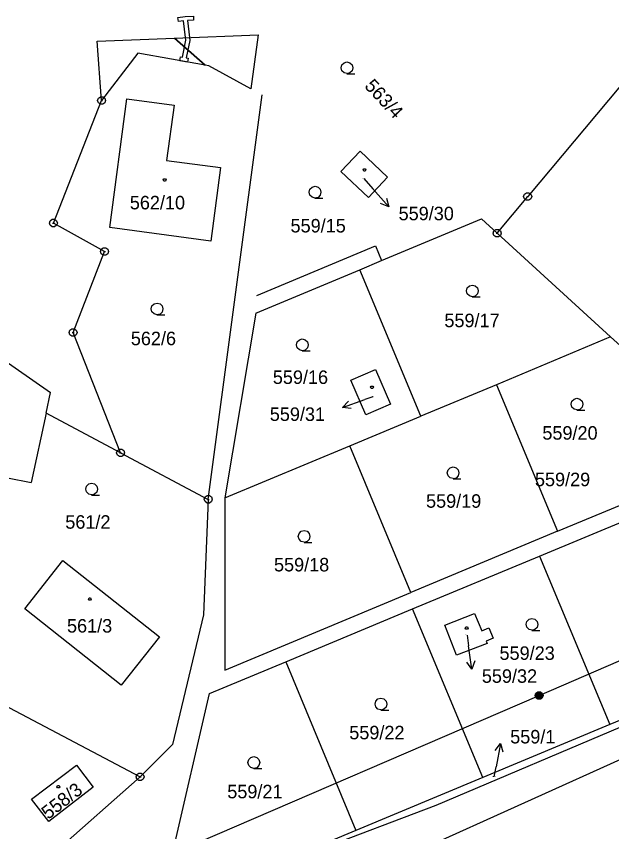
# Model space of a CAD drawing. Extents: x -759699 to -757730, y -1172308 to -1170857.
# Drawn here: x -759171.2 to -759096.2, y -1171620.5 to -1171517.8 of the extents above; entities that cross this region are included whole.
import ezdxf

# ---------------------------------------------------------------- set-up
doc = ezdxf.new("R2010")
doc.units = 0
for name, color, linetype in [('Vrstva 1', 7, 'Continuous'), ('Vrstva 12', 7, 'Continuous'), ('Vrstva 13', 7, 'Continuous'), ('Vrstva 2', 7, 'Continuous'), ('Vrstva 3', 7, 'Continuous'), ('Vrstva 4', 7, 'Continuous'), ('Vrstva 5', 7, 'Continuous'), ('Vrstva 6', 7, 'Continuous'), ('Vrstva 7', 7, 'Continuous'), ('Vrstva 8', 7, 'Continuous')]:
    doc.layers.add(name, color=color, linetype=linetype)

msp = doc.modelspace()

# ---------------------------------------------------------------- linework, layer by layer
at = {"layer": 'Vrstva 1'}
for p, q in [((-759093.5, -1171524.55), (-759106.82, -1171540.51)), ((-759159.44, -1171544.39), (-759157.28, -1171528.2)), ((-759157.28, -1171528.2), (-759151.34, -1171528.99)), ((-759147.03, -1171578.64), (-759140.26, -1171527.68)), ((-759140.26, -1171527.68), (-759140.26, -1171527.68)), ((-759140.26, -1171527.68), (-759140.26, -1171527.68)), ((-759166.53, -1171543.84), (-759160.46, -1171528.4)), ((-759160.46, -1171528.4), (-759160.46, -1171528.4)), ((-759151.34, -1171528.99), (-759152.28, -1171535.96)), ((-759127.92, -1171534.77), (-759130.34, -1171537.33)), ((-759127.92, -1171534.77), (-759124.46, -1171538.06)), ((-759152.28, -1171535.96), (-759145.48, -1171536.83)), ((-759145.48, -1171536.83), (-759146.71, -1171546.12)), ((-759130.34, -1171537.33), (-759126.87, -1171540.61)), ((-759124.46, -1171538.06), (-759126.87, -1171540.61)), ((-759110.66, -1171545.12), (-759106.82, -1171540.51)), ((-759106.82, -1171540.51), (-759106.82, -1171540.51)), ((-759125.21, -1171548.56), (-759112.63, -1171543.32)), ((-759112.63, -1171543.32), (-759112.63, -1171543.32)), ((-759112.63, -1171543.32), (-759110.66, -1171545.12)), ((-759160.09, -1171547.43), (-759166.53, -1171543.84)), ((-759146.71, -1171546.12), (-759159.44, -1171544.39)), ((-759110.66, -1171545.12), (-759096.41, -1171558.16)), ((-759140.91, -1171552.94), (-759125.98, -1171546.71)), ((-759125.98, -1171546.71), (-759125.21, -1171548.56)), ((-759164.05, -1171557.64), (-759160.09, -1171547.43)), ((-759127.97, -1171549.71), (-759125.21, -1171548.56)), ((-759141.06, -1171555.17), (-759127.97, -1171549.71)), ((-759120.29, -1171568.18), (-759127.97, -1171549.71)), ((-759140.91, -1171552.94), (-759140.91, -1171552.94)), ((-759141.06, -1171555.17), (-759144.93, -1171578.46)), ((-759179.26, -1171556.57), (-759166.9, -1171565.2)), ((-759158.07, -1171572.78), (-759164.05, -1171557.64)), ((-759096.41, -1171558.16), (-759110.76, -1171564.21)), ((-759078.48, -1171574.58), (-759096.41, -1171558.16)), ((-759129.07, -1171563.62), (-759125.97, -1171562.29)), ((-759125.97, -1171562.29), (-759124.09, -1171566.66)), ((-759127.19, -1171568.01), (-759129.07, -1171563.62)), ((-759167.45, -1171567.78), (-759166.9, -1171565.2)), ((-759110.76, -1171564.21), (-759120.29, -1171568.18)), ((-759110.76, -1171564.21), (-759103.07, -1171582.66)), ((-759124.09, -1171566.66), (-759127.19, -1171568.01)), ((-759167.45, -1171567.78), (-759169.31, -1171576.53)), ((-759158.07, -1171572.78), (-759167.45, -1171567.78)), ((-759129.22, -1171571.91), (-759120.29, -1171568.18)), ((-759144.93, -1171578.46), (-759129.22, -1171571.91)), ((-759121.53, -1171590.36), (-759129.22, -1171571.91)), ((-759158.07, -1171572.78), (-759147.03, -1171578.64)), ((-759172.32, -1171575.91), (-759169.31, -1171576.53)), ((-759103.07, -1171582.66), (-759087.39, -1171576.13)), ((-759144.93, -1171578.46), (-759144.97, -1171600.14)), ((-759147.03, -1171578.64), (-759147.64, -1171593.18)), ((-759105.35, -1171585.79), (-759089.39, -1171579.13)), ((-759103.07, -1171582.66), (-759121.53, -1171590.36)), ((-759170.14, -1171592.43), (-759165.33, -1171586.33)), ((-759165.33, -1171586.33), (-759153.19, -1171595.95)), ((-759121.32, -1171592.45), (-759105.35, -1171585.79)), ((-759105.35, -1171585.79), (-759096.5, -1171607.02)), ((-759144.97, -1171600.14), (-759121.53, -1171590.36)), ((-759158, -1171602.06), (-759170.14, -1171592.43)), ((-759137.29, -1171599.1), (-759121.32, -1171592.45)), ((-759112.47, -1171613.68), (-759121.32, -1171592.45)), ((-759147.64, -1171593.18), (-759151.53, -1171609.52)), ((-759117.27, -1171594.48), (-759113.51, -1171593)), ((-759113.51, -1171593), (-759112.58, -1171595.21)), ((-759064.19, -1171594.2), (-759118.37, -1171617.22)), ((-759115.77, -1171598.28), (-759117.27, -1171594.48)), ((-759112.58, -1171595.21), (-759111.7, -1171594.84)), ((-759111.7, -1171594.84), (-759111.17, -1171596.13)), ((-759153.19, -1171595.95), (-759158, -1171602.06)), ((-759111.93, -1171596.78), (-759115.77, -1171598.28)), ((-759111.17, -1171596.13), (-759112.04, -1171596.5)), ((-759112.04, -1171596.5), (-759111.93, -1171596.78)), ((-759146.88, -1171603.11), (-759137.29, -1171599.1)), ((-759137.29, -1171599.1), (-759128.44, -1171620.34)), ((-759080.54, -1171600.36), (-759096.5, -1171607.02)), ((-759153.26, -1171630.69), (-759146.88, -1171603.11)), ((-759172.84, -1171604.48), (-759155.62, -1171613.61)), ((-759096.5, -1171607.02), (-759112.47, -1171613.68)), ((-759151.53, -1171609.52), (-759155.62, -1171613.61)), ((-759169.27, -1171616.41), (-759163.64, -1171612.11)), ((-759163.64, -1171612.11), (-759161.51, -1171614.89)), ((-759183.56, -1171638.31), (-759155.62, -1171613.61)), ((-759112.47, -1171613.68), (-759128.44, -1171620.34)), ((-759161.51, -1171614.89), (-759167.12, -1171619.22)), ((-759167.12, -1171619.22), (-759169.27, -1171616.41)), ((-759118.37, -1171617.22), (-759136.99, -1171624.23)), ((-759128.44, -1171620.34), (-759153.26, -1171630.69))]:
    msp.add_line(p, q, dxfattribs=at)
at = {"layer": 'Vrstva 12'}
for p, q in [((-759159.44, -1171544.39), (-759157.28, -1171528.2)), ((-759157.28, -1171528.2), (-759151.34, -1171528.99)), ((-759151.34, -1171528.99), (-759152.28, -1171535.96)), ((-759127.92, -1171534.77), (-759130.34, -1171537.33)), ((-759127.92, -1171534.77), (-759124.46, -1171538.06)), ((-759152.28, -1171535.96), (-759145.48, -1171536.83)), ((-759145.48, -1171536.83), (-759146.71, -1171546.12)), ((-759130.34, -1171537.33), (-759126.87, -1171540.61)), ((-759124.46, -1171538.06), (-759126.87, -1171540.61)), ((-759146.71, -1171546.12), (-759159.44, -1171544.39)), ((-759129.07, -1171563.62), (-759125.97, -1171562.29)), ((-759125.97, -1171562.29), (-759124.09, -1171566.66)), ((-759127.19, -1171568.01), (-759129.07, -1171563.62)), ((-759124.09, -1171566.66), (-759127.19, -1171568.01)), ((-759170.14, -1171592.43), (-759165.33, -1171586.33)), ((-759165.33, -1171586.33), (-759153.19, -1171595.95)), ((-759158, -1171602.06), (-759170.14, -1171592.43)), ((-759117.27, -1171594.48), (-759113.51, -1171593)), ((-759113.51, -1171593), (-759112.58, -1171595.21)), ((-759115.77, -1171598.28), (-759117.27, -1171594.48)), ((-759112.58, -1171595.21), (-759111.7, -1171594.84)), ((-759111.7, -1171594.84), (-759111.17, -1171596.13)), ((-759153.19, -1171595.95), (-759158, -1171602.06)), ((-759111.93, -1171596.78), (-759115.77, -1171598.28)), ((-759111.17, -1171596.13), (-759112.04, -1171596.5)), ((-759112.04, -1171596.5), (-759111.93, -1171596.78)), ((-759169.27, -1171616.41), (-759163.64, -1171612.11)), ((-759163.64, -1171612.11), (-759161.51, -1171614.89)), ((-759161.51, -1171614.89), (-759167.12, -1171619.22)), ((-759167.12, -1171619.22), (-759169.27, -1171616.41))]:
    msp.add_line(p, q, dxfattribs=at)
at = {"layer": 'Vrstva 13'}
for p, q in [((-759150.86, -1171517.94), (-759149.96, -1171517.8)), ((-759150.78, -1171518.44), (-759150.86, -1171517.94)), ((-759149.96, -1171517.8), (-759148.89, -1171517.79)), ((-759148.89, -1171517.79), (-759148.89, -1171518.29)), ((-759150.16, -1171518.34), (-759150.78, -1171518.44)), ((-759149.9, -1171520.48), (-759150.16, -1171518.34)), ((-759148.89, -1171518.29), (-759149.66, -1171518.3)), ((-759149.66, -1171518.3), (-759149.4, -1171520.47)), ((-759161.02, -1171520.93), (-759151.27, -1171520.54)), ((-759160.46, -1171528.4), (-759161.02, -1171520.93)), ((-759151.27, -1171520.54), (-759140.77, -1171520.12)), ((-759147.44, -1171523.94), (-759151.27, -1171520.54)), ((-759151.27, -1171520.54), (-759147.44, -1171523.94)), ((-759150.29, -1171522.93), (-759149.86, -1171520.8)), ((-759149.86, -1171520.8), (-759149.9, -1171520.48)), ((-759149.36, -1171520.82), (-759149.8, -1171523.02)), ((-759149.4, -1171520.47), (-759149.36, -1171520.82)), ((-759140.77, -1171520.12), (-759141.67, -1171526.91)), ((-759155.89, -1171522.45), (-759160.46, -1171528.4)), ((-759147.44, -1171523.94), (-759155.89, -1171522.45)), ((-759150.63, -1171523.38), (-759150.55, -1171522.89)), ((-759150.55, -1171522.89), (-759150.29, -1171522.93)), ((-759149.8, -1171523.02), (-759149.56, -1171523.06)), ((-759149.56, -1171523.06), (-759149.65, -1171523.55)), ((-759149.65, -1171523.55), (-759150.63, -1171523.38)), ((-759146.95, -1171524.03), (-759147.44, -1171523.94)), ((-759141.67, -1171526.91), (-759146.95, -1171524.03))]:
    msp.add_line(p, q, dxfattribs=at)
at = {"layer": 'Vrstva 3'}
for points in [[(-759129.56, -1171525.01), (-759129.94, -1171524.91), (-759130.21, -1171524.64), (-759130.31, -1171524.27), (-759130.21, -1171523.9), (-759129.94, -1171523.63), (-759129.57, -1171523.53), (-759129.2, -1171523.63), (-759128.93, -1171523.9), (-759128.83, -1171524.28), (-759128.93, -1171524.66), (-759129.2, -1171524.93), (-759129.58, -1171525.03), (-759128.58, -1171525.03)], [(-759133.58, -1171540.68), (-759133.96, -1171540.58), (-759134.23, -1171540.31), (-759134.33, -1171539.94), (-759134.23, -1171539.57), (-759133.96, -1171539.3), (-759133.59, -1171539.2), (-759133.22, -1171539.3), (-759132.95, -1171539.57), (-759132.85, -1171539.95), (-759132.95, -1171540.33), (-759133.22, -1171540.6), (-759133.6, -1171540.7), (-759132.6, -1171540.7)], [(-759113.78, -1171553.12), (-759114.16, -1171553.02), (-759114.43, -1171552.75), (-759114.53, -1171552.38), (-759114.43, -1171552.01), (-759114.16, -1171551.74), (-759113.79, -1171551.64), (-759113.42, -1171551.74), (-759113.15, -1171552.01), (-759113.05, -1171552.39), (-759113.15, -1171552.77), (-759113.42, -1171553.04), (-759113.8, -1171553.14), (-759112.8, -1171553.14)], [(-759153.47, -1171555.39), (-759153.85, -1171555.29), (-759154.12, -1171555.02), (-759154.22, -1171554.65), (-759154.12, -1171554.28), (-759153.85, -1171554.01), (-759153.48, -1171553.91), (-759153.11, -1171554.01), (-759152.84, -1171554.28), (-759152.74, -1171554.66), (-759152.84, -1171555.04), (-759153.11, -1171555.31), (-759153.49, -1171555.41), (-759152.49, -1171555.41)], [(-759135.19, -1171559.91), (-759135.57, -1171559.81), (-759135.84, -1171559.54), (-759135.94, -1171559.17), (-759135.84, -1171558.8), (-759135.57, -1171558.53), (-759135.2, -1171558.43), (-759134.83, -1171558.53), (-759134.56, -1171558.8), (-759134.46, -1171559.18), (-759134.56, -1171559.56), (-759134.83, -1171559.83), (-759135.21, -1171559.93), (-759134.21, -1171559.93)], [(-759100.61, -1171567.38), (-759100.99, -1171567.28), (-759101.26, -1171567.01), (-759101.36, -1171566.64), (-759101.26, -1171566.27), (-759100.99, -1171566), (-759100.62, -1171565.9), (-759100.25, -1171566), (-759099.98, -1171566.27), (-759099.88, -1171566.65), (-759099.98, -1171567.03), (-759100.25, -1171567.3), (-759100.63, -1171567.4), (-759099.63, -1171567.4)], [(-759116.2, -1171576.03), (-759116.58, -1171575.93), (-759116.85, -1171575.66), (-759116.95, -1171575.29), (-759116.85, -1171574.92), (-759116.58, -1171574.65), (-759116.21, -1171574.55), (-759115.84, -1171574.65), (-759115.57, -1171574.92), (-759115.47, -1171575.3), (-759115.57, -1171575.68), (-759115.84, -1171575.95), (-759116.22, -1171576.05), (-759115.22, -1171576.05)], [(-759161.71, -1171578.08), (-759162.09, -1171577.98), (-759162.36, -1171577.71), (-759162.46, -1171577.34), (-759162.36, -1171576.97), (-759162.09, -1171576.7), (-759161.72, -1171576.6), (-759161.35, -1171576.7), (-759161.08, -1171576.97), (-759160.98, -1171577.35), (-759161.08, -1171577.73), (-759161.35, -1171578), (-759161.73, -1171578.1), (-759160.73, -1171578.1)], [(-759134.96, -1171584.04), (-759135.34, -1171583.94), (-759135.61, -1171583.67), (-759135.71, -1171583.3), (-759135.61, -1171582.93), (-759135.34, -1171582.66), (-759134.97, -1171582.56), (-759134.6, -1171582.66), (-759134.33, -1171582.93), (-759134.23, -1171583.31), (-759134.33, -1171583.69), (-759134.6, -1171583.96), (-759134.98, -1171584.06), (-759133.98, -1171584.06)], [(-759106.27, -1171595.12), (-759106.65, -1171595.02), (-759106.92, -1171594.75), (-759107.02, -1171594.38), (-759106.92, -1171594.01), (-759106.65, -1171593.74), (-759106.28, -1171593.64), (-759105.91, -1171593.74), (-759105.64, -1171594.01), (-759105.54, -1171594.39), (-759105.64, -1171594.77), (-759105.91, -1171595.04), (-759106.29, -1171595.14), (-759105.29, -1171595.14)], [(-759125.29, -1171605.16), (-759125.67, -1171605.06), (-759125.94, -1171604.79), (-759126.04, -1171604.42), (-759125.94, -1171604.05), (-759125.67, -1171603.78), (-759125.3, -1171603.68), (-759124.93, -1171603.78), (-759124.66, -1171604.05), (-759124.56, -1171604.43), (-759124.66, -1171604.81), (-759124.93, -1171605.08), (-759125.31, -1171605.18), (-759124.31, -1171605.18)], [(-759141.29, -1171612.53), (-759141.67, -1171612.43), (-759141.94, -1171612.16), (-759142.04, -1171611.79), (-759141.94, -1171611.42), (-759141.67, -1171611.15), (-759141.3, -1171611.05), (-759140.93, -1171611.15), (-759140.66, -1171611.42), (-759140.56, -1171611.8), (-759140.66, -1171612.18), (-759140.93, -1171612.45), (-759141.31, -1171612.55), (-759140.31, -1171612.55)]]:
    msp.add_lwpolyline(points, dxfattribs=at)
at = {"layer": 'Vrstva 4'}
msp.add_line((-759072.45, -1171601.16), (-759121.76, -1171623.41), dxfattribs=at)
at = {"layer": 'Vrstva 5'}
for points in [[(-759127.27, -1171537), (-759127.18, -1171537.15), (-759127.27, -1171537.3), (-759127.45, -1171537.3), (-759127.54, -1171537.15), (-759127.45, -1171537)], [(-759152.43, -1171538.26), (-759152.34, -1171538.41), (-759152.43, -1171538.56), (-759152.61, -1171538.56), (-759152.7, -1171538.41), (-759152.61, -1171538.26)], [(-759126.33, -1171564.37), (-759126.24, -1171564.52), (-759126.33, -1171564.67), (-759126.51, -1171564.67), (-759126.6, -1171564.52), (-759126.51, -1171564.37)], [(-759161.85, -1171591.06), (-759161.76, -1171591.21), (-759161.85, -1171591.36), (-759162.03, -1171591.36), (-759162.12, -1171591.21), (-759162.03, -1171591.06)], [(-759114.41, -1171594.7), (-759114.32, -1171594.85), (-759114.41, -1171595), (-759114.59, -1171595), (-759114.68, -1171594.85), (-759114.59, -1171594.7)], [(-759165.82, -1171614.69), (-759165.73, -1171614.84), (-759165.82, -1171614.99), (-759166, -1171614.99), (-759166.09, -1171614.84), (-759166, -1171614.69)]]:
    msp.add_lwpolyline(points, close=True, dxfattribs=at)
at = {"layer": 'Vrstva 6'}
for p, q in [((-759105.39, -1171603.36), (-759038.87, -1171574.49)), ((-759224.97, -1171654.89), (-759105.39, -1171603.36))]:
    msp.add_line(p, q, dxfattribs=at)
msp.add_lwpolyline([(-759105.54, -1171602.88), (-759105.23, -1171602.88), (-759104.98, -1171603.06), (-759104.88, -1171603.35), (-759104.98, -1171603.64), (-759105.23, -1171603.82), (-759105.54, -1171603.82), (-759105.79, -1171603.64), (-759105.89, -1171603.35), (-759105.79, -1171603.06), (-759105.54, -1171602.88), (-759105.51, -1171602.92), (-759105.27, -1171602.92), (-759105.11, -1171603), (-759105.67, -1171603), (-759105.75, -1171603.08), (-759105.03, -1171603.08), (-759105.03, -1171603.16), (-759105.75, -1171603.16), (-759105.79, -1171603.24), (-759104.99, -1171603.24), (-759104.95, -1171603.32), (-759105.83, -1171603.32), (-759105.83, -1171603.4), (-759104.95, -1171603.4), (-759104.98, -1171603.48), (-759105.79, -1171603.48), (-759105.78, -1171603.56), (-759104.97, -1171603.56), (-759105.02, -1171603.64), (-759105.74, -1171603.64), (-759105.66, -1171603.72), (-759105.1, -1171603.72), (-759105.21, -1171603.8), (-759105.55, -1171603.8)], dxfattribs=at)
at = {"layer": 'Vrstva 7'}
for p, q in [((-759127.44, -1171538.24), (-759126.3, -1171539.53)), ((-759124.312, -1171541.777), (-759126.3, -1171539.53)), ((-759130.138, -1171567.061), (-759127.31, -1171566.06)), ((-759126.33, -1171565.71), (-759127.31, -1171566.06)), ((-759114.45, -1171595.73), (-759114.26, -1171597.08)), ((-759113.834, -1171600.05), (-759114.26, -1171597.08)), ((-759110.264, -1171609.39), (-759110.81, -1171612.34)), ((-759111.04, -1171613.61), (-759110.81, -1171612.34))]:
    msp.add_line(p, q, dxfattribs=at)
for points in [[(-759124.6, -1171540.696), (-759124.312, -1171541.777), (-759125.349, -1171541.359)], [(-759129.029, -1171567.199), (-759130.138, -1171567.061), (-759129.362, -1171566.256)], [(-759113.481, -1171598.989), (-759113.834, -1171600.05), (-759114.471, -1171599.131)], [(-759110.937, -1171610.282), (-759110.264, -1171609.39), (-759109.954, -1171610.465)]]:
    msp.add_lwpolyline(points, dxfattribs=at)
at = {"layer": 'Vrstva 8'}
for p, q in [((-759160.58, -1171528.4), (-759160.34, -1171528.4)), ((-759106.94, -1171540.51), (-759106.7, -1171540.51)), ((-759166.65, -1171543.84), (-759166.41, -1171543.84)), ((-759110.78, -1171545.12), (-759110.54, -1171545.12)), ((-759160.21, -1171547.43), (-759159.97, -1171547.43)), ((-759164.17, -1171557.64), (-759163.93, -1171557.64)), ((-759158.19, -1171572.78), (-759157.95, -1171572.78)), ((-759147.15, -1171578.64), (-759146.91, -1171578.64)), ((-759155.74, -1171613.61), (-759155.5, -1171613.61))]:
    msp.add_line(p, q, dxfattribs=at)
for points in [[(-759160.31, -1171527.92), (-759160.06, -1171528.1), (-759159.96, -1171528.39), (-759160.06, -1171528.68), (-759160.31, -1171528.86), (-759160.62, -1171528.86), (-759160.87, -1171528.68), (-759160.97, -1171528.39), (-759160.87, -1171528.1), (-759160.62, -1171527.92)], [(-759106.67, -1171540.03), (-759106.42, -1171540.21), (-759106.32, -1171540.5), (-759106.42, -1171540.79), (-759106.67, -1171540.97), (-759106.98, -1171540.97), (-759107.23, -1171540.79), (-759107.33, -1171540.5), (-759107.23, -1171540.21), (-759106.98, -1171540.03)], [(-759166.38, -1171543.36), (-759166.13, -1171543.54), (-759166.03, -1171543.83), (-759166.13, -1171544.12), (-759166.38, -1171544.3), (-759166.69, -1171544.3), (-759166.94, -1171544.12), (-759167.04, -1171543.83), (-759166.94, -1171543.54), (-759166.69, -1171543.36)], [(-759110.51, -1171544.64), (-759110.26, -1171544.82), (-759110.16, -1171545.11), (-759110.26, -1171545.4), (-759110.51, -1171545.58), (-759110.82, -1171545.58), (-759111.07, -1171545.4), (-759111.17, -1171545.11), (-759111.07, -1171544.82), (-759110.82, -1171544.64)], [(-759159.94, -1171546.95), (-759159.69, -1171547.13), (-759159.59, -1171547.42), (-759159.69, -1171547.71), (-759159.94, -1171547.89), (-759160.25, -1171547.89), (-759160.5, -1171547.71), (-759160.6, -1171547.42), (-759160.5, -1171547.13), (-759160.25, -1171546.95)], [(-759163.9, -1171557.16), (-759163.65, -1171557.34), (-759163.55, -1171557.63), (-759163.65, -1171557.92), (-759163.9, -1171558.1), (-759164.21, -1171558.1), (-759164.46, -1171557.92), (-759164.56, -1171557.63), (-759164.46, -1171557.34), (-759164.21, -1171557.16)], [(-759157.92, -1171572.3), (-759157.67, -1171572.48), (-759157.57, -1171572.77), (-759157.67, -1171573.06), (-759157.92, -1171573.24), (-759158.23, -1171573.24), (-759158.48, -1171573.06), (-759158.58, -1171572.77), (-759158.48, -1171572.48), (-759158.23, -1171572.3)], [(-759146.88, -1171578.16), (-759146.63, -1171578.34), (-759146.53, -1171578.63), (-759146.63, -1171578.92), (-759146.88, -1171579.1), (-759147.19, -1171579.1), (-759147.44, -1171578.92), (-759147.54, -1171578.63), (-759147.44, -1171578.34), (-759147.19, -1171578.16)], [(-759155.47, -1171613.13), (-759155.22, -1171613.31), (-759155.12, -1171613.6), (-759155.22, -1171613.89), (-759155.47, -1171614.07), (-759155.78, -1171614.07), (-759156.03, -1171613.89), (-759156.13, -1171613.6), (-759156.03, -1171613.31), (-759155.78, -1171613.13)]]:
    msp.add_lwpolyline(points, close=True, dxfattribs=at)

# ---------------------------------------------------------------- texts
at = {"layer": 'Vrstva 2'}
for s, rotation, p in [('563/4', 312.89225, (-759127.458, -1171526.657)), ('558/3', 37.87251, (-759167.194, -1171619.035))]:
    msp.add_text(s, height=1.7, rotation=rotation, dxfattribs=at).set_placement(p)
for s, height, p in [('559/30', 0.1, (-759127.695, -1171538.24)), ('562/10', 1.7, (-759156.912, -1171542.11)), ('559/15', 1.7, (-759136.675, -1171545.02)), ('559/17', 1.7, (-759117.308, -1171556.95)), ('562/6', 1.7, (-759156.784, -1171559.22)), ('559/16', 1.7, (-759138.908, -1171564.1)), ('559/31', 0.1, (-759126.563, -1171565.71)), ('559/20', 1.7, (-759104.977, -1171571.12)), ('559/19', 1.7, (-759119.618, -1171579.7)), ('561/2', 1.7, (-759165.036, -1171582.34)), ('559/18', 1.7, (-759138.758, -1171587.72)), ('561/3', 1.7, (-759164.819, -1171595.42)), ('559/32', 0.1, (-759114.707, -1171595.73)), ('559/23', 1.7, (-759110.367, -1171598.86)), ('559/22', 1.7, (-759129.284, -1171608.87)), ('559/1', 0.1, (-759111.227, -1171613.61)), ('559/21', 1.7, (-759144.642, -1171616.3))]:
    msp.add_text(s, height=height, dxfattribs=at).set_placement(p)
at = {"layer": 'Vrstva 7'}
for s, p in [('559/30', (-759123.073, -1171543.48)), ('559/31', (-759139.288, -1171568.76)), ('559/29', (-759105.908, -1171576.98)), ('559/32', (-759112.593, -1171601.75)), ('559/1', (-759109.023, -1171609.39))]:
    msp.add_text(s, height=1.7, dxfattribs=at).set_placement(p)

doc.saveas('drawing.dxf')
